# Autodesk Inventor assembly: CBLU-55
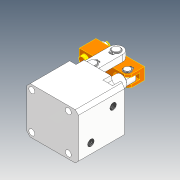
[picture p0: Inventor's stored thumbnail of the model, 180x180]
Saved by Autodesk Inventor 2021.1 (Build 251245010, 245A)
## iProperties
Created: 2019-05
Part Number: CBLU-55
Description: STEP AP214
Document SubType Name: Assembly
Designer: user
Title: CBLU-55.STEP
Revision Number: ÈÎºÎ
Sending System: SolidWorks 2016
Preprocessor: SwSTEP 2.0
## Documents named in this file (11)
- D:\Vault_2016\Projekty\Clamptek\Hydraulic\CBLU\CBLU-55\Inventor\CBLU-55\CBLU-55.iam
- D:\Vault_2016\Projekty\Clamptek\Hydraulic\CBLU\CBLU-55\Inventor\CBLU-55\CBLU-55C±¾Ìå_1_1_1_1.ipt
- D:\Vault_2016\Projekty\Clamptek\Hydraulic\CBLU\CBLU-55\Inventor\CBLU-55\changxiao.ipt
- D:\Vault_2016\Projekty\Clamptek\Hydraulic\CBLU\CBLU-55\Inventor\CBLU-55\duanxiao.ipt
- D:\Vault_2016\Projekty\Clamptek\Hydraulic\CBLU\CBLU-55\Inventor\CBLU-55\huosaigan_4_1.ipt
- D:\Vault_2016\Projekty\Clamptek\Hydraulic\CBLU\CBLU-55\Inventor\CBLU-55\liangan.ipt
- D:\Vault_2016\Projekty\Clamptek\Hydraulic\CBLU\CBLU-55\Inventor\CBLU-55\yabi.ipt
- D:\Vault_2016\Projekty\Clamptek\Hydraulic\CBLU\CBLU-55\Inventor\CBLU-55\kahuang.ipt
- D:\Vault_2016\Projekty\Clamptek\Hydraulic\CBLU\CBLU-55\Inventor\CBLU-55\kahuang01.ipt
- D:\Vault_2016\Projekty\Clamptek\Hydraulic\CBLU\CBLU-55\Inventor\CBLU-55\luogan.ipt
- D:\Vault_2016\Projekty\Clamptek\Hydraulic\CBLU\CBLU-55\Inventor\CBLU-55\luomu.ipt
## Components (16 placed, 16 different names)
1. CBLU-55C±¾Ìå_1_1_1_1_1
2. changxiao_2
3. duanxiao_3
4. huosaigan_4_1_4
5. liangan_5
6. yabi_6
7. liangan_7
8. changxiao_8
9. kahuang_9
10. kahuang_10
11. kahuang_11
12. kahuang_12
13. kahuang01_13
14. kahuang01_14
15. luogan_15
16. luomu_16
